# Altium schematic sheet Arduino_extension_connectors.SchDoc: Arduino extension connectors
size A4; Date: Not used; ApprovedBy: Not used; CheckedBy: Not used; Author: Not used; CompanyName: STMicroelectronics; DrawnBy: Not used; Engineer: Not used; Organization: Not used; Address1: Not used; Address2: Not used; Address3: Not used; Address4: Not used; DocumentNumber: 5; Revision: Not used; SheetNumber: 5; SheetTotal: 8
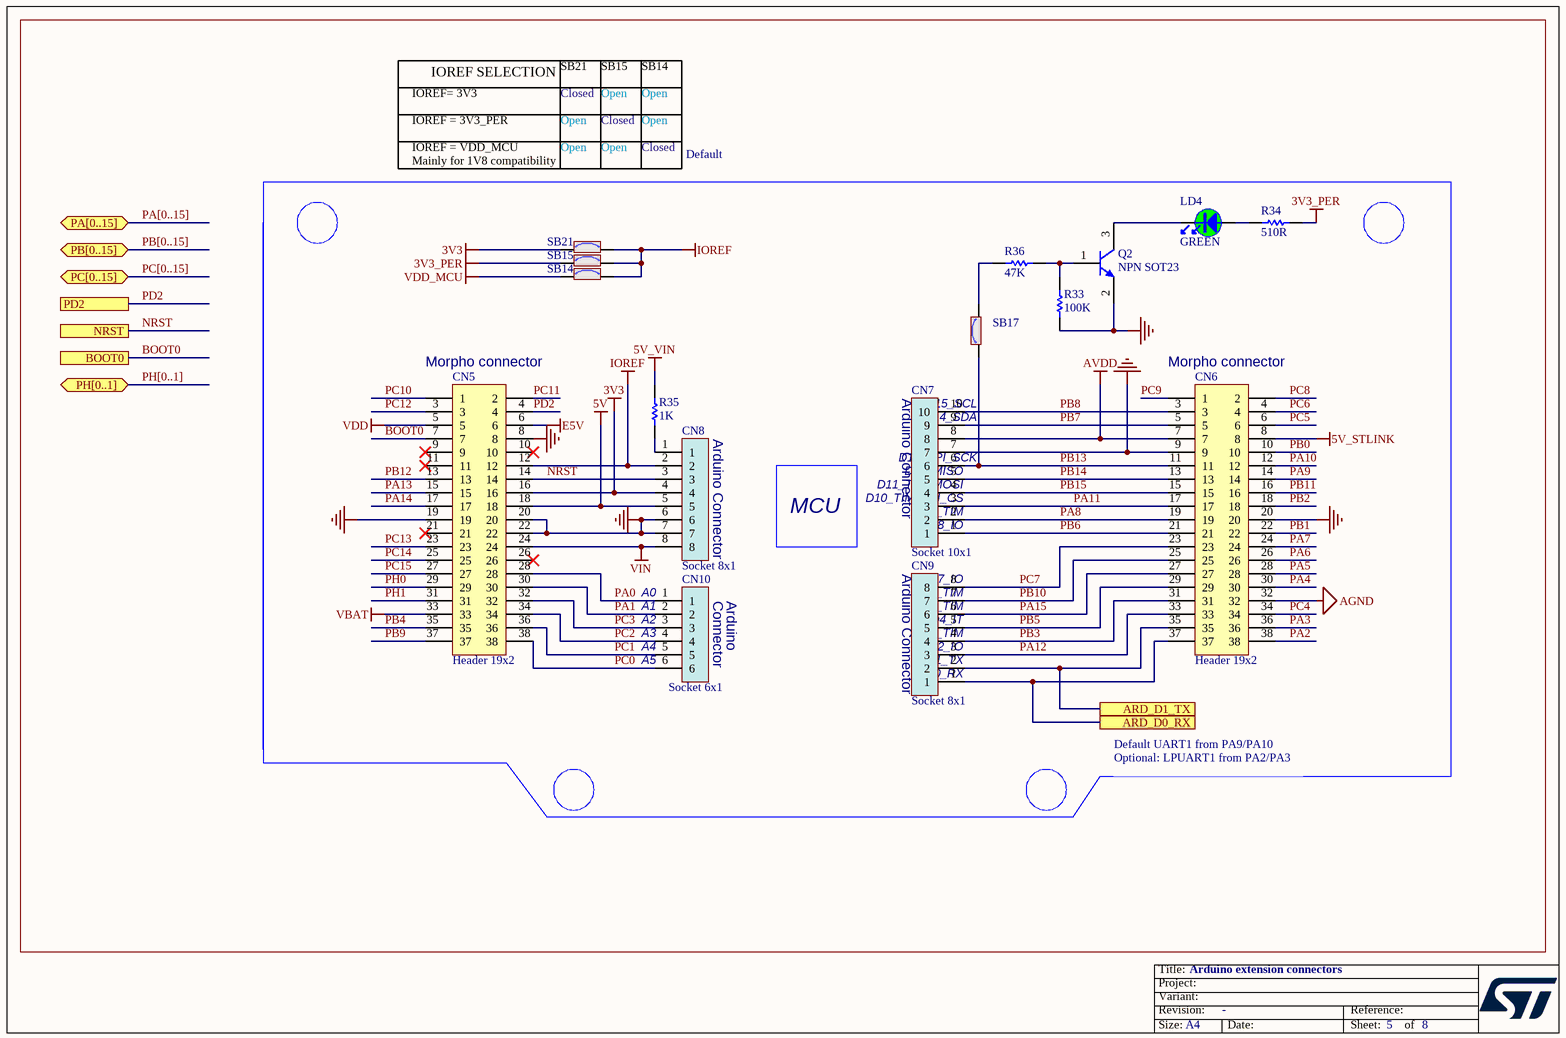
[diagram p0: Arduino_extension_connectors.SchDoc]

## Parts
CN5  Header 19x2  [CON_SAMTEC_TSW-119-09-X-D]
CN6  Header 19x2  [CON_SAMTEC_TSW-119-09-X-D]
CN7  Socket 10x1  [CON_SAMTEC_SSW-110-03-X-S]
CN8  Socket 8x1  [CON_SAMTEC_SSW-108-03-X-S]
CN9  Socket 8x1  [CON_SAMTEC_SSW-108-03-X-S]
CN10  Socket 6x1  [CON_SAMTEC_SSW-106-03-X-S]
LD4  value GREEN  [LED_0603_GREEN]  (hidden comment: LED_green)
Q2  value NPN SOT23  [NPN_SOT23]  (hidden comment: 9013-SOT23)
R33  value 100K  [R0603]  (hidden comment: Resistor)
R34  value 510R  [R0603]  (hidden comment: Resistor)
R35  value 1K  [R0603]  (hidden comment: Resistor)
R36  value 47K  [R0603]  (hidden comment: Resistor)
SB14  SB_ON  [SOLDER-BRIDGE_R0603-0R]  (value not drawn)
SB15  SB_ON  [SOLDER-BRIDGE_R0603-0R]  (value not drawn)
SB17  SB_ON  [SOLDER-BRIDGE_R0603-0R]  (value not drawn)
SB21  SB_ON  [SOLDER-BRIDGE_R0603-0R]  (value not drawn)

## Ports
ARD_D0_RX, ARD_D1_TX, BOOT0, NRST, PA[0..15] (bidir), PB[0..15] (bidir), PC[0..15] (bidir), PD2, PH[0..1] (bidir)

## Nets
3V3: CN5.16 CN8.4 SB21.2
3V3_PER: R34.1 SB15.2
5V: CN5.18 CN8.5
5V_STLINK: CN6.8
5V_VIN: R35.2
AGND: CN6.32
AVDD: CN6.7 CN7.8
E5V: CN5.6
GND: CN5.8 CN5.19 CN5.20 CN5.22 CN6.9 CN6.20 CN7.7 CN8.6 CN8.7 Q2.2(E) R33.1
IOREF: CN5.12 CN8.2 SB14.1 SB15.1 SB21.1
VBAT: CN5.33
VDD: CN5.5
VDD_MCU: SB14.2
VIN: CN5.24 CN8.8
ARD_D0_RX: CN6.37 CN9.1 ; port ARD_D0_RX
ARD_D1_TX: CN6.35 CN9.2 ; port ARD_D1_TX
BOOT0: CN5.7 ; port BOOT0
NRST: CN5.14 CN8.3 ; port NRST
PA0: CN5.28 CN10.1
PA1: CN5.30 CN10.2
PA2: CN6.38
PA3: CN6.36
PA4: CN6.30
PA5: CN6.28
PA6: CN6.26
PA7: CN6.24
PA8: CN6.19 CN7.2
PA9: CN6.14
PA10: CN6.12
PA11: CN6.17 CN7.3
PA12: CN6.33 CN9.3
PA13: CN5.15
PA14: CN5.17
PA15: CN6.27 CN9.6
PB0: CN6.10
PB1: CN6.22
PB2: CN6.18
PB3: CN6.31 CN9.4
PB4: CN5.35
PB5: CN6.29 CN9.5
PB6: CN6.21 CN7.1
PB7: CN6.5 CN7.9
PB8: CN6.3 CN7.10
PB9: CN5.37
PB10: CN6.25 CN9.7
PB11: CN6.16
PB12: CN5.13
PB13: CN6.11 CN7.6 SB17.1
PB14: CN6.13 CN7.5
PB15: CN6.15 CN7.4
PC0: CN5.38 CN10.6
PC1: CN5.36 CN10.5
PC2: CN5.34 CN10.4
PC3: CN5.32 CN10.3
PC4: CN6.34
PC5: CN6.6
PC6: CN6.4
PC7: CN6.23 CN9.8
PC8: CN6.2
PC9: CN6.1
PC10: CN5.1
PC11: CN5.2
PC12: CN5.3
PC13: CN5.23
PC14: CN5.25
PC15: CN5.27
PD2: CN5.4 ; port PD2
PH0: CN5.29
PH1: CN5.31
NetCN8_1: CN8.1 R35.1
NetLD4_1: LD4.1 R34.2
NetLD4_2: LD4.2 Q2.3(C)
NetQ2_1: Q2.1(B) R33.2 R36.2
NetR36_1: R36.1 SB17.2

Not connected (* = marked no-connect by the designer): CN5 9* 10* 11* 21* 26*

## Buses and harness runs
bus PA[0..15] = port PA[0..15]
bus PB[0..15] = port PB[0..15]
bus PC[0..15] = port PC[0..15]
bus PH[0..1] = port PH[0..1]

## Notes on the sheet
- IOREF= 3V3
- IOREF SELECTION
- SB21
- Closed
- SB15
- Open
- SB14
- IOREF = 3V3_PER
- IOREF = VDD_MCU
- Mainly for 1V8 compatibility
- Default
- (near CN5) Morpho connector
- (near CN6) Morpho connector
- (near CN8) Arduino Connector
- (near CN7) Arduino Connector
- (near CN7) D14_SDA
- D15_SCL
- MCU
- (near CN7) D9_TIM
- (near CN7) D10_TIM_SPI_CS
- (near CN7) D12_MISO
- (near CN7) D11_TIM_MOSI
- (near CN7) D13_SPI_SCK
- (near CN9) Arduino Connector
- (near CN9) D7_IO
- (near CN7) D8_IO
- (near CN10) A0
- (near CN10) A1
- (near CN10) A2
- (near CN10) A3
- (near CN10) A4
- (near CN10) Connector
- (near CN10) Arduino
- (near CN9) D2_IO
- (near CN9) D4_IT
- (near CN9) D3_TIM
- (near CN9) D5_TIM
- (near CN9) D6_TIM
- (near CN10) A5
- (near CN9) D0_RX
- (near CN9) D1_TX
- Default UART1 from PA9/PA10
  Optional: LPUART1 from PA2/PA3

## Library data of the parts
CN5 CN6 = MCD-00213: Header, 19x2, 2,54mm, VR, TH, Height 5.84mm/10.16mm; Manufacturer_Part_Number: TSW-119-09-G-D; Manufacturer: SAMTEC; Part_Type: Connector; Part_Preference: Recommended
CN7 = MCD-00262: Socket, 10x1, 2.54mm, VR, TH, Height 8.51mm/10mm; Part_Type: Connector; Part_Preference: Recommended; Manufacturer: SAMTEC; Manufacturer_Part_Number: SSW-110-03-G-S
CN8 CN9 = MCD-00261: Socket, 8x1, 2.54mm, VR, TH, Height 8.51mm/10mm; Part_Type: Connector; Part_Preference: Recommended; Manufacturer: SAMTEC; Manufacturer_Part_Number: SSW-108-03-G-S
CN10 = MCD-00260: Socket, 6x1, 2.54mm, VR, TH, Height 8.51mm/10mm; Manufacturer_Part_Number: SSW-106-03-G-S; Manufacturer: SAMTEC; Part_Type: Connector; Part_Preference: Recommended
LD4 = MCD-02900: LED, Green, 2V, 25mA, 0603, SMD; Part_Type: Display; Part_Preference: Recommended; Manufacturer: EVERLIGHT; Manufacturer_Part_Number: 19-213SYGC/S530-E2/5T; Full_Alternate_Internal_Part_Number: MCD-00320; Partial_Alternate_Internal_Part_Number: MCD-00050; Component_Country_Of_Origin: China; ShowFields: YES; ID: 5016
Q2 = MCD-00073: NPN Bipolar Transistor; Part_Type: IC; Manufacturer_Part_Number: BSR14; Manufacturer: ON SEMICONDUCTOR; Part_Preference: Recommended; Alternate_Manufacturer_Part_Number: MMBT2222LT1G / MMBT2222ALT1G / MMBT2222ALT3G
R33 = MCD-00223: Resistor,100K,0603,1%,1/10W; Manufacturer_Part_Number: RC0603FR-07100KL; Manufacturer: YAGEO; Part_Preference: Recommended
R34 = MCD-00225: Resistor,510R,0603,1%,1/10W; Manufacturer_Part_Number: RC0603FR-07510RL; Manufacturer: YAGEO; Part_Preference: Recommended
R35 = MCD-00070: Resistor,1K,0603,1%,1/10W; Manufacturer_Part_Number: RC0603FR-071KL; Manufacturer: YAGEO; Part_Preference: Recommended
R36 = MCD-00222: Resistor,47K,0603,1%,1/10W; Manufacturer_Part_Number: RC0603FR-0747KL; Manufacturer: YAGEO; Part_Preference: Recommended
SB14 SB15 SB17 SB21 = MCD-00071: Solder Bridge ON; Part_Type: Misc; Part_Preference: Recommended; Manufacturer: YAGEO; Manufacturer_Part_Number: RC0603JR-070RL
